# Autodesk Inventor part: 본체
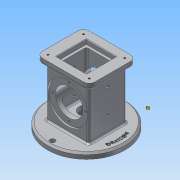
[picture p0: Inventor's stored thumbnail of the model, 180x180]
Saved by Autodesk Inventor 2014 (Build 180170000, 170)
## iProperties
Created: 2019-08
Part Number: 본체
Material: 알루미늄 6061
Document SubType Name: Modeling
Designer: NET
Density: 2.71 g/cm^3
Appearance: 알루미늄 - 평지
Mass: 1041.14 g
Surface Area: 787.451 cm^2
Volume: 384.185 cm^3
Author: NET
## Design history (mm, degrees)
sketch "스케치1"
  geometry: L1 (37, -33)-(-37, -33); L2 (-37, -33)-(-37, 33); L3 (-37, 33)-(37, 33); L4 (37, 33)-(37, -33); L5 (37, -33)-(-37, 33); L6 (-37, -33)-(37, 33); 1 further point
  constraints: 12 end point, 2 midpoint, 2 parallel, 1 horizontal, 1 perpendicular
  dimensions: "d0" = 74 distance of L2.end L3.end; "d1" = 66 distance of L3.end L1.start
extrude "돌출1" new body sketch "스케치1" distance "d2" = 108; taper "d3" = 0 deg
node "작업 평면1"
sketch "스케치2"
  geometry: L1 (-33, 0)-(-33, 108) reference; L2 (33, 0)-(33, 108) reference; L3 (33, 0)-(33, 108) reference; L4 (-33, 54)-(33, 54); L5 (-33, 0)-(33, 0) reference; L6 (-33, 89)-(-30, 89); L7 (-30, 89)-(-30, 78); L8 (-30, 78)-(30, 78); L9 (30, 78)-(30, 89); L10 (30, 89)-(33, 89); 1 further point
  constraints: 12 end point, 3 parallel, 3 perpendicular, 2 midpoint, 2 point on line, 1 collinear
  dimensions: "d4" = 54 distance between parallel lines of L5 L4; "d5" = 70 diameter of L6 L4; "d6" = 48 diameter of L8 L4; "d7" = 70 diameter of L10 L4; "d8" = 3 distance of L6.start L6.end
revolve "회전1" sketch "스케치2" stored, may be unused: angle "d9" = 90 deg
sketch "스케치3"
  geometry: L1 (26, 26)-(-26, 26); L2 (-26, 26)-(-26, -26); L3 (-26, -26)-(26, -26); L4 (26, -26)-(26, 26); L5 (26, 26)-(-26, -26); L6 (-26, 26)-(26, -26); L7 (22, 22)-(-22, 22); L8 (-22, 22)-(-22, -22); L9 (-22, -22)-(22, -22); L10 (22, -22)-(22, 22); L11 (22, 22)-(-22, -22); L12 (-22, 22)-(22, -22); 1 further point
  constraints: 24 end point, 4 midpoint, 4 parallel, 3 perpendicular, 2 horizontal, 1 point on line
  dimensions: "d10" = 52 distance of L1.end L2.end; "d11" = 44 distance of L7.end L8.end
extrude "돌출2" cut sketch "스케치3" distance "d12" = 8; taper "d13" = 0 deg
extrude "돌출3" cut sketch "스케치3" distance "d14" = 82; taper "d15" = 0 deg
node "작업 평면2"
sketch "스케치4"
  geometry: C1 r 25 at (0, 0); C2 r 12.5 at (0, 0); 1 further point
  constraints: 2 centre point, 2 coincident
  dimensions: "d16" = 50 diameter of C1; "d17" = 25 diameter of C2
extrude "돌출4" cut sketch "스케치4" distance "d18" = 18; taper "d19" = 0 deg
extrude "돌출5" cut sketch "스케치4" stored distance "d20" = 18; taper "d21" = 0 deg
sketch "스케치5"
  geometry: C1 r 67.5 at (0, 0); 1 further point
  constraints: 1 centre point, 1 coincident
  dimensions: "d22" = 135 diameter of C1
extrude "돌출6" join sketch "스케치5" distance "d23" = 10; taper "d24" = 0 deg
sketch "스케치6"
  geometry: C1 r 12.5 at (0, 0) reference; C2 r 12.5 at (0, 0)
  constraints: 1 centre point, 1 coincident, 1 concentric
extrude "돌출7" cut sketch "스케치6" distance "d25" = 10; taper "d26" = 0 deg
sketch "스케치7"
  geometry: L1 (-37, -33)-(37, -33) reference; L2 (37, -33)-(37, 33) reference; L3 (37, 33)-(-37, 33) reference; L4 (-37, 33)-(-37, -33) reference; L5 (46, -41)-(-46, -41); L6 (-46, -41)-(-46, 41); L7 (-46, 41)-(46, 41); L8 (46, 41)-(46, -41); L9 (46, -41)-(-46, 41); L10 (-46, -41)-(46, 41); 1 further point
  constraints: 12 end point, 2 midpoint, 2 parallel, 1 horizontal, 1 perpendicular
  dimensions: "d27" = 82 distance of L7.end L5.start; "d28" = 92 distance of L6.end L7.end
extrude "돌출8" join sketch "스케치7" distance "d29" = 10; taper "d30" = 0 deg
sketch "스케치8"
  geometry: L1 (36, -31)-(-36, -31); L2 (-36, -31)-(-36, 31); L3 (-36, 31)-(36, 31); L4 (36, 31)-(36, -31); L5 (36, -31)-(-36, 31); L6 (-36, -31)-(36, 31); 5 further points
  constraints: 12 end point, 4 coincident, 2 midpoint, 2 parallel, 1 horizontal, 1 perpendicular
  dimensions: "d31" = 72 distance of L2.end L3.end; "d32" = 62 distance of L3.end L1.start
hole "구멍1" sketch "스케치8" diameter "d33" = 3.242; stored, may be unused: countersink angle "d37" = 90 deg, drill point angle "d39" = 118 deg; dims "d34" = 4, "d35" = 4, "d36" = 2, "d38" = 6
hole "구멍2" sketch "스케치8" diameter "d43" = 3.242; stored, may be unused: countersink angle "d47" = 90 deg, drill point angle "d49" = 118 deg; dims "d44" = 4, "d45" = 4, "d46" = 2, "d48" = 6
hole "구멍3" sketch "스케치8" diameter "d50" = 3.242; stored, may be unused: countersink angle "d54" = 90 deg, drill point angle "d56" = 118 deg; dims "d51" = 4, "d52" = 4, "d53" = 2, "d55" = 6
hole "구멍4" sketch "스케치8" diameter "d57" = 3.242; stored, may be unused: countersink angle "d61" = 90 deg, drill point angle "d63" = 118 deg; dims "d58" = 4, "d59" = 4, "d60" = 2, "d62" = 6
sketch "스케치9"
  geometry: L1 (-88, 74)-(-88, -8) reference; L2 (10, -34.5)-(10, 100.5) reference; 4 further points
  constraints: 4 horizontal alignment, 1 midpoint
  dimensions: "d64" = 37 distance from line of L2 point (-27, 33); "d65" = 43 distance of point (-27, 33) point (-70, 33)
hole "구멍5" sketch "스케치9" at (-70, 33), (-27, 33) diameter "d66" = 4.917; stored, may be unused: countersink angle "d70" = 90 deg, drill point angle "d72" = 118 deg; dims "d67" = 4, "d68" = 4, "d69" = 2, "d71" = 6
sketch "스케치10" dims "d73" = 58
  geometry: C1 r 35 at (0, 0) reference; C2 r 24 at (0, 0) reference; 3 further points
  constraints: 2 vertical alignment, 1 coincident, 2 other
hole "구멍6" sketch "스케치10" at (0, 29) diameter "d74" = 3.242; stored, may be unused: countersink angle "d78" = 90 deg, drill point angle "d80" = 118 deg; dims "d75" = 4, "d76" = 4, "d77" = 2, "d79" = 6
node "작업 평면3"
sketch "스케치11"
  geometry: 1 further point
sketch "스케치12"
  geometry: C1 r 67.5 at (0, 0) reference; C2 r 4.5 at (-59, 0); C3 r 4.5 at (0, 59); C4 r 4.5 at (0, -59); A1 r 59 centre (0, 0) between (-59, 0) and (0, 59)
  constraints: 4 centre point, 3 point on circle, 2 vertical alignment, 1 coincident, 1 horizontal alignment
  dimensions: "d85" = 118 diameter of A1; "d86" = 9 diameter of C2; "d87" = 9 diameter of C4; "d88" = 9 diameter of C3
extrude "돌출9" cut sketch "스케치12" stored distance "d89" = 10; taper "d90" = 0 deg
chamfer "모따기1" distance "d91" = 3; stored, may be unused: second distance "d92" = 2, angle "d93" = 45 deg
chamfer "모따기2" distance "d94" = 1; stored, may be unused: second distance "d95" = 2, angle "d96" = 45 deg
fillet "모깎기1" dims "d97" = 3
fillet "모깎기2" dims "d98" = 3
fillet "모깎기3" dims "d99" = 3
sketch "스케치13"
  geometry: 1 further point
sketch "스케치14"
  geometry: C1 r 12.5 at (0, 0) reference; C2 r 67.5 at (0, 0) reference; C3 r 25 at (0, 0)
  constraints: 1 centre point, 1 coincident
  dimensions: "d100" = 50 diameter of C3
extrude "돌출10" cut sketch "스케치14" distance "d101" = 18; taper "d102" = 0 deg
fillet "모깎기4" dims "d103" = 3
fillet "모깎기5" dims "d104" = 3
fillet "모깎기6" dims "d105" = 3
fillet "모깎기7" dims "d106" = 10
fillet "모깎기8" dims "d107" = 3
node "작업 평면4"
sketch "스케치15"
  geometry: 1 further point
fillet "모깎기9" dims "d109" = 3
sketch "스케치17"
  geometry: C1 r 64.5 at (0, 0) reference; C2 r 59 at (0, 0)
  constraints: 1 centre point, 1 coincident, 1 other
  dimensions: "d110" = 118 diameter of C2
feature "엠보싱1" sketch "스케치17" dims "d111" = 0.5, "d112" = 0
node "솔리드1"
pattern_linear "직사각형 패턴1" dims "d42" = 72
pattern_circular "원형 패턴1" dims angle "d82" = 360 deg
mirror "대칭1"
